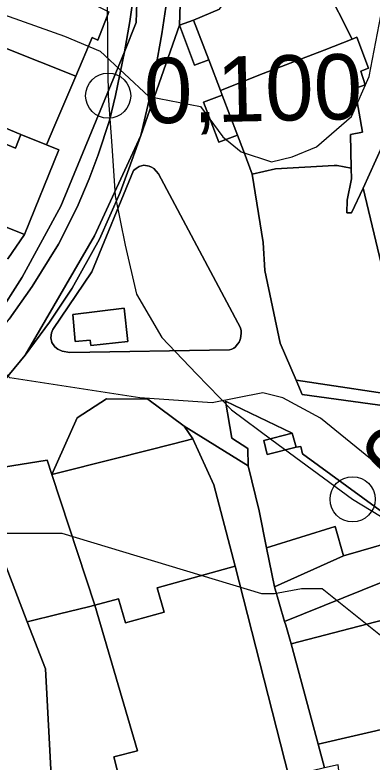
# Model space of a CAD drawing. Extents: x -510989 to -501240, y -1184665 to -1176098.
# Drawn here: x -504684.9 to -504613.7, y -1182308.5 to -1182159.8 of the extents above; entities that cross this region are included whole.
import ezdxf

# ---------------------------------------------------------------- set-up
doc = ezdxf.new("R2010")
doc.units = 0
for name, color, linetype in [('ostatni_plocha_x_ostatni_komunikace', 7, 'Continuous'), ('ostatni_plocha_x_silnice', 7, 'Continuous'), ('ostatni_plocha_x_zelen', 7, 'Continuous'), ('STAV_zaplavove_uzemi', 7, 'Continuous'), ('trasovani_toku', 7, 'Continuous'), ('vrstevnice_01', 7, 'Continuous'), ('vrstevnice_02', 7, 'Continuous'), ('zahrada', 7, 'Continuous'), ('zastavena_plocha_a_nadvori', 7, 'Continuous')]:
    doc.layers.add(name, color=color, linetype=linetype)

msp = doc.modelspace()

# ---------------------------------------------------------------- linework, layer by layer
at = {"layer": 'ostatni_plocha_x_ostatni_komunikace'}
for points in [[(-504644.16, -1182158.62), (-504649.3, -1182160.78), (-504652.14, -1182161.81), (-504650.82, -1182121.52)], [(-504660.37, -1182149.27), (-504662.02, -1182161.09), (-504663.05, -1182167.12), (-504675.77, -1182197.83), (-504683.43, -1182211.95), (-504688.49, -1182219.81)], [(-504611.7, -1182185.91), (-504615.53, -1182194.22), (-504617.83, -1182199.16), (-504618.74, -1182199.13), (-504618.72, -1182196.62), (-504617.81, -1182192.4), (-504617.88, -1182190.27), (-504618.05, -1182183.56), (-504615.66, -1182183.07), (-504617.19, -1182174.42), (-504615.09, -1182173.64), (-504615.99, -1182170.94), (-504614.48, -1182170.36), (-504616.78, -1182164.17), (-504617.71, -1182164.55), (-504623.08, -1182153.88)], [(-504686.3, -1182208.31), (-504682.98, -1182203.49), (-504676.16, -1182186.61), (-504678.6, -1182185.63), (-504676.92, -1182181.68), (-504672.79, -1182171.96), (-504669.53, -1182164.28), (-504668.4, -1182164.75), (-504666.17, -1182159.11)], [(-504697.03, -1182244.56), (-504682.84, -1182227.46), (-504677.99, -1182220.94), (-504673.48, -1182214.15), (-504668.02, -1182204.42), (-504663.93, -1182195.11), (-504662.22, -1182190.36), (-504659.83, -1182183.78), (-504652.14, -1182161.81), (-504649.09, -1182169.74), (-504646.29, -1182168.67), (-504643.94, -1182174.78), (-504643.58, -1182175.72), (-504647.32, -1182177.14), (-504644.29, -1182185.09), (-504640.55, -1182183.66), (-504639.35, -1182186.82), (-504639.21, -1182187.14), (-504637.6, -1182191.44), (-504635.43, -1182205.06), (-504635.12, -1182210.65), (-504632.08, -1182225.08), (-504628.86, -1182232.48), (-504627.64, -1182235.34), (-504603.94, -1182238.59)], [(-504609.96, -1182259.99), (-504627.58, -1182247.12), (-504627.95, -1182245.67), (-504628.83, -1182245.8), (-504629.64, -1182243.02), (-504642.92, -1182236.66), (-504641.7, -1182244.02), (-504638.47, -1182246.06), (-504638.43, -1182249.54), (-504651.18, -1182241.6), (-504658.4, -1182236.23), (-504666.64, -1182236.16), (-504672.47, -1182239.98), (-504677.55, -1182251.26), (-504678.47, -1182248.35), (-504692.63, -1182250.62)]]:
    msp.add_lwpolyline(points, dxfattribs=at)
for points in [[(-504659.22, -1182189.67), (-504660.13, -1182189.92), (-504660.76, -1182190.32), (-504661.28, -1182190.71), (-504669.6, -1182210.92), (-504677.32, -1182222.39), (-504677.62, -1182223.05), (-504677.73, -1182224), (-504677.52, -1182224.94), (-504676.96, -1182225.8), (-504676.36, -1182226.26), (-504675.47, -1182226.7), (-504673.99, -1182226.97), (-504642.15, -1182226.44), (-504641.69, -1182226.31), (-504641.26, -1182226.11), (-504641.02, -1182225.89), (-504640.52, -1182225.31), (-504640.25, -1182224.92), (-504640.09, -1182224.57), (-504639.97, -1182224.15), (-504639.88, -1182223.69), (-504639.82, -1182223.09), (-504639.84, -1182222.64), (-504639.94, -1182222.03), (-504656.29, -1182191.36), (-504657.22, -1182190.32), (-504657.67, -1182190.03), (-504658.16, -1182189.86)], [(-504651.18, -1182241.6), (-504638.43, -1182249.54), (-504636.23, -1182258.44), (-504634.77, -1182265.81), (-504633.21, -1182273.56), (-504631.16, -1182280.51), (-504630.95, -1182281.21), (-504629.89, -1182284.92), (-504629.69, -1182285.64), (-504624.48, -1182304.88), (-504623.21, -1182309.63), (-504630.34, -1182311.33), (-504641.03, -1182269.51), (-504645.27, -1182253.28), (-504649.47, -1182244.16)]]:
    msp.add_lwpolyline(points, close=True, dxfattribs=at)
at = {"layer": 'ostatni_plocha_x_silnice'}
for points in [[(-504650.82, -1182121.52), (-504652.14, -1182161.81), (-504659.83, -1182183.78), (-504658.17, -1182176.68), (-504656.9, -1182170.57), (-504655.64, -1182163.51), (-504654.43, -1182155.52), (-504653.3, -1182146.7), (-504652.48, -1182138.59)], [(-504662.02, -1182161.09), (-504660.37, -1182149.27), (-504660.74, -1182161.27), (-504663.05, -1182167.12)], [(-504659.83, -1182183.78), (-504662.22, -1182190.36), (-504663.93, -1182195.11), (-504668.02, -1182204.42), (-504673.48, -1182214.15), (-504677.99, -1182220.94), (-504682.84, -1182227.46), (-504669.04, -1182203.7)]]:
    msp.add_lwpolyline(points, close=True, dxfattribs=at)
for points in [[(-504766.11, -1182313.77), (-504760.55, -1182307.61), (-504749.86, -1182296.14), (-504746.43, -1182292.4), (-504737.71, -1182282.64), (-504734.35, -1182278.85), (-504728.65, -1182272.06), (-504708.46, -1182247.87), (-504697.85, -1182235.08), (-504692.31, -1182228.28), (-504686.08, -1182220.29), (-504681.44, -1182213.79), (-504676.25, -1182205.38), (-504672.53, -1182198), (-504670.11, -1182192.37), (-504668.31, -1182187.63), (-504666.07, -1182180.74), (-504664.83, -1182175.8), (-504663.05, -1182167.12), (-504660.74, -1182161.27), (-504660.37, -1182149.27)], [(-504654.43, -1182155.52), (-504655.64, -1182163.51), (-504656.9, -1182170.57), (-504658.17, -1182176.68), (-504659.83, -1182183.78), (-504669.04, -1182203.7), (-504682.84, -1182227.46), (-504697.03, -1182244.56), (-504701.01, -1182249.26), (-504722, -1182272.99), (-504747.79, -1182303.57), (-504752.28, -1182308.37), (-504756.37, -1182312.89)], [(-504688.49, -1182219.81), (-504683.43, -1182211.95), (-504675.77, -1182197.83), (-504663.05, -1182167.12), (-504664.83, -1182175.8), (-504666.07, -1182180.74), (-504668.31, -1182187.63), (-504670.11, -1182192.37), (-504672.53, -1182198), (-504676.25, -1182205.38), (-504681.44, -1182213.79), (-504686.08, -1182220.29)]]:
    msp.add_lwpolyline(points, dxfattribs=at)
at = {"layer": 'ostatni_plocha_x_zelen'}
for points in [[(-504649.3, -1182160.78), (-504646.29, -1182168.67), (-504649.09, -1182169.74), (-504652.14, -1182161.81)], [(-504643.58, -1182175.72), (-504640.55, -1182183.66), (-504644.29, -1182185.09), (-504647.32, -1182177.14)], [(-504659.22, -1182189.67), (-504658.16, -1182189.86), (-504657.67, -1182190.03), (-504657.22, -1182190.32), (-504656.29, -1182191.36), (-504639.94, -1182222.03), (-504639.84, -1182222.64), (-504639.82, -1182223.09), (-504639.88, -1182223.69), (-504639.97, -1182224.15), (-504640.09, -1182224.57), (-504640.25, -1182224.92), (-504640.52, -1182225.31), (-504641.02, -1182225.89), (-504641.26, -1182226.11), (-504641.69, -1182226.31), (-504642.15, -1182226.44), (-504673.99, -1182226.97), (-504675.47, -1182226.7), (-504676.36, -1182226.26), (-504676.96, -1182225.8), (-504677.52, -1182224.94), (-504677.73, -1182224), (-504677.62, -1182223.05), (-504677.32, -1182222.39), (-504669.6, -1182210.92), (-504661.28, -1182190.71), (-504660.76, -1182190.32), (-504660.13, -1182189.92)], [(-504673.37, -1182219.36), (-504672.91, -1182224.76), (-504669.9, -1182224.48), (-504669.78, -1182225.58), (-504662.43, -1182224.74), (-504663.12, -1182218.12)]]:
    msp.add_lwpolyline(points, close=True, dxfattribs=at)
at = {"layer": 'STAV_zaplavove_uzemi'}
for points in [[(-502250.32, -1184002.61), (-502355.07, -1183875.41), (-502442.37, -1183790.61), (-502477.29, -1183700.82), (-502532.16, -1183578.61), (-502567.08, -1183448.91), (-502626.05, -1183402.34), (-502705.41, -1183380.59), (-502814.2, -1183349.87), (-502882.03, -1183297.39), (-502931.95, -1183237.24), (-503042.02, -1183107.97), (-503139.64, -1183018.94), (-503222.14, -1182957.59), (-503308.56, -1182839.96), (-503316.24, -1182784.92), (-503330.32, -1182756.77), (-503348.24, -1182719.65), (-503334.16, -1182651.82), (-503323.92, -1182595.5), (-503313.68, -1182526.39), (-503294.1, -1182480.5), (-503251.86, -1182396.03), (-503229.34, -1182314.37), (-503216.1, -1182227.15), (-503242.43, -1182174.5), (-503271.86, -1182129.59), (-503287.34, -1182081.58), (-503343.88, -1182028.1), (-503361.79, -1182008.91), (-503396.35, -1181952.59), (-503442.43, -1181933.39), (-503497.46, -1181888.6), (-503525.62, -1181860.44), (-503528.18, -1181837.4), (-503548.66, -1181767.01), (-503558.9, -1181729.89), (-503576.82, -1181682.53), (-503578.1, -1181621.1), (-503567.86, -1181572.46), (-503552.5, -1181536.63), (-503538.04, -1181458.36), (-503518.33, -1181411.9), (-503509.88, -1181341.51), (-503497.21, -1181207.63), (-503499.77, -1181097.56), (-503498.02, -1181031.35), (-503510.82, -1180970.85), (-503549.22, -1180952.23), (-503571.32, -1180940.6), (-503605.07, -1180937.11), (-503651.61, -1180939.44), (-503671.39, -1180917.33), (-503679.53, -1180892.89), (-503713.27, -1180871.95), (-503727.24, -1180859.15), (-503734.22, -1180833.55), (-503728.4, -1180799.81), (-503741.2, -1180770.72), (-503722.82, -1180725.17), (-503721.54, -1180703.41), (-503731.78, -1180697.01), (-503767.61, -1180699.57), (-503790.65, -1180697.01), (-503817.53, -1180697.01), (-503861.04, -1180686.77), (-503889.2, -1180675.25), (-503900.72, -1180668.85), (-503953.2, -1180679.09), (-503997.99, -1180697.01), (-504063.27, -1180722.61), (-504109.34, -1180749.49), (-504142.62, -1180776.36), (-504177.18, -1180796.84), (-504211.73, -1180817.32), (-504414.98, -1180961.5), (-504472.7, -1180998.11), (-504544.51, -1181068.5), (-504600.82, -1181143.12), (-504621.94, -1181196.62), (-504641.65, -1181267.01), (-504660.25, -1181350.62), (-504634.7, -1181398.32), (-504617.66, -1181447.72), (-504600.62, -1181492.01), (-504587, -1181548.23), (-504592.11, -1181628.29), (-504569.96, -1181682.81), (-504568.26, -1181664.07), (-504554.63, -1181621.48), (-504547.82, -1181597.63)], [(-504826.46, -1182247.73), (-504827.62, -1182204.68), (-504817.15, -1182165.12), (-504791.55, -1182113.93), (-504727.56, -1182034.81), (-504708.94, -1182017.35), (-504669.38, -1181991.76), (-504649.6, -1181961.5), (-504628.66, -1181917.29), (-504601.9, -1181867.26), (-504597.24, -1181809.08), (-504585.16, -1181766.79), (-504596.8, -1181741.4), (-504604.2, -1181726.59), (-504633.82, -1181658.9), (-504646.51, -1181600.72), (-504660.26, -1181556.29), (-504751.04, -1181459.08), (-504798.4, -1181384.84), (-504826.55, -1181347.73), (-504862.39, -1181315.73), (-504866.23, -1181265.81), (-504862.39, -1181205.66), (-504853.43, -1181164.7), (-504793.92, -1181116.47), (-504755.84, -1181064.64), (-504725.17, -1181018.1), (-504649.01, -1180947.23), (-504594, -1180900.69), (-504545.35, -1180879.53), (-504377.38, -1180832.83), (-504317.01, -1180808.36), (-504368.93, -1180802.59), (-504426.63, -1180826.63), (-504542.02, -1180859.32)], [(-504547.82, -1181597.63), (-504529.08, -1181677.7), (-504510.34, -1181762.87), (-504510.34, -1181805.46), (-504503.52, -1181848.05), (-504522.26, -1181902.56), (-504557.31, -1181989.81), (-504582.91, -1182010.28), (-504608.51, -1182029.48), (-504618.75, -1182071.72), (-504632.83, -1182096.04), (-504648.18, -1182115.24), (-504664.82, -1182122.91), (-504685.3, -1182130.59), (-504727.54, -1182144.67), (-504745.46, -1182181.79), (-504758.25, -1182222.75), (-504758.25, -1182257.3), (-504807.19, -1182292.7), (-504828.34, -1182288.47), (-504827.28, -1182244.04)], [(-504574.97, -1181692.93), (-504558.07, -1181754.88), (-504562.29, -1181804.15), (-504563.7, -1181856.24), (-504570.74, -1181913.97), (-504583.41, -1181961.83), (-504617.2, -1182002.66), (-504652.4, -1182051.94), (-504665.07, -1182080.1), (-504696.04, -1182099.81), (-504738.28, -1182108.25), (-504752.36, -1182122.33), (-504767.85, -1182144.86), (-504780.52, -1182142.04), (-504787.55, -1182173.02), (-504781.92, -1182218.07), (-504783.33, -1182247.63), (-504788.96, -1182265.94), (-504808.67, -1182277.2), (-504832.61, -1182281.42)], [(-504824.03, -1182251.79), (-504806.11, -1182251.79), (-504808.67, -1182227.48), (-504803.55, -1182203.16), (-504807.39, -1182181.4), (-504806.11, -1182154.52), (-504795.88, -1182126.36), (-504783.08, -1182119.97), (-504770.28, -1182113.56), (-504754.92, -1182091.81), (-504726.76, -1182079.01), (-504689.64, -1182070.05), (-504667.89, -1182041.89), (-504634.61, -1181997.1), (-504615.41, -1181959.98), (-504602.61, -1181927.98), (-504596.21, -1181880.63), (-504594.68, -1181823.86), (-504583.41, -1181774.59), (-504590.45, -1181740.8), (-504600.31, -1181726.72)]]:
    msp.add_spline(points, degree=3, dxfattribs=at)
at = {"layer": 'trasovani_toku'}
for p, q in [((-504666.52, -1182155.83), (-504666.44, -1182165.83)), ((-504666.44, -1182165.83), (-504666.32, -1182175.83)), ((-504666.32, -1182175.83), (-504665.58, -1182185.81)), ((-504665.58, -1182185.81), (-504664.91, -1182195.78)), ((-504664.91, -1182195.78), (-504662.95, -1182205.59)), ((-504662.95, -1182205.59), (-504660.69, -1182215.33)), ((-504660.69, -1182215.33), (-504655.63, -1182223.96)), ((-504655.63, -1182223.96), (-504648.73, -1182231.19)), ((-504648.73, -1182231.19), (-504641.75, -1182238.36)), ((-504641.75, -1182238.36), (-504633.74, -1182244.34)), ((-504633.74, -1182244.34), (-504625.68, -1182250.25)), ((-504625.68, -1182250.25), (-504617.62, -1182256.17)), ((-504617.62, -1182256.17), (-504609.06, -1182261.35))]:
    msp.add_line(p, q, dxfattribs=at)
for centre in [(-504666.32, -1182175.83), (-504617.62, -1182256.17)]:
    msp.add_circle(centre, 4.5, dxfattribs=at)
at = {"layer": 'vrstevnice_01'}
msp.add_lwpolyline([(-504613, -1182249), (-504624, -1182240), (-504631.5, -1182236), (-504635.5, -1182235), (-504645.59, -1182237), (-504660, -1182236), (-504685.91, -1182232), (-504692.59, -1182225), (-504698.41, -1182222), (-504710.5, -1182217), (-504718.81, -1182216), (-504728.81, -1182218), (-504737, -1182223), (-504749.41, -1182234), (-504775.41, -1182271), (-504783.09, -1182289), (-504788.69, -1182335)], dxfattribs=at)
at = {"layer": 'vrstevnice_02'}
for points in [[(-504689.09, -1182159), (-504675, -1182164), (-504667.91, -1182167), (-504658.19, -1182176), (-504647.91, -1182178), (-504643.5, -1182184), (-504639.81, -1182187), (-504633.81, -1182189), (-504629.69, -1182188), (-504624.81, -1182186), (-504617.81, -1182180), (-504614.31, -1182172), (-504610.69, -1182153)], [(-504602.41, -1182291), (-504623.69, -1182274), (-504627.81, -1182274), (-504633.19, -1182275), (-504635.69, -1182275), (-504675.5, -1182263), (-504691.81, -1182263), (-504700.09, -1182266), (-504704.31, -1182268), (-504708.69, -1182272), (-504713.19, -1182277), (-504723, -1182294), (-504726.81, -1182296), (-504731.59, -1182297), (-504737.09, -1182307), (-504738.5, -1182311), (-504739.41, -1182328)]]:
    msp.add_lwpolyline(points, dxfattribs=at)
at = {"layer": 'zahrada'}
for points in [[(-504628.86, -1182232.48), (-504605, -1182236.03), (-504603.94, -1182238.59), (-504627.64, -1182235.34)], [(-504658.4, -1182236.23), (-504651.18, -1182241.6), (-504649.47, -1182244.16), (-504653.3, -1182245.12), (-504664.58, -1182247.96), (-504677.55, -1182251.26), (-504672.47, -1182239.98), (-504666.64, -1182236.16)], [(-504634.77, -1182265.81), (-504621.06, -1182261.61), (-504619.41, -1182267.4), (-504633.21, -1182273.56)], [(-504615.98, -1182266.42), (-504608.88, -1182264.4), (-504604.03, -1182269.55), (-504631.16, -1182280.51), (-504633.21, -1182273.56), (-504619.41, -1182267.4)], [(-504641.03, -1182269.51), (-504630.34, -1182311.33), (-504641.6, -1182314.32), (-504651.02, -1182316.82), (-504662.04, -1182319.75), (-504665.19, -1182307.45), (-504660.45, -1182306.23), (-504668.96, -1182277.25), (-504664.24, -1182275.96), (-504662.9, -1182280.78), (-504655.19, -1182278.64), (-504656.53, -1182273.82)], [(-504604.03, -1182269.55), (-504600.8, -1182271.69), (-504599.46, -1182277.02), (-504629.89, -1182284.92), (-504630.95, -1182281.21), (-504631.16, -1182280.51)], [(-504668.96, -1182277.25), (-504660.45, -1182306.23), (-504665.19, -1182307.45), (-504662.04, -1182319.75), (-504656.53, -1182341.24), (-504650.6, -1182363.05), (-504641.21, -1182396.51), (-504652.49, -1182400.2), (-504665.38, -1182366.99), (-504669.71, -1182355.06), (-504666.12, -1182354.21), (-504667.75, -1182347.35), (-504670.44, -1182348.03), (-504672.44, -1182341.25), (-504666.74, -1182340.05), (-504671.77, -1182319.92), (-504677.14, -1182321.18), (-504678.79, -1182289.89), (-504682.43, -1182280.53), (-504676.03, -1182278.97), (-504670.23, -1182277.56)], [(-504624.48, -1182304.88), (-504594.03, -1182297.85), (-504589.17, -1182310.48), (-504580.13, -1182308.14), (-504568.81, -1182326.98), (-504579.19, -1182329.55), (-504616.94, -1182338.59), (-504620.51, -1182309), (-504623.21, -1182309.63)]]:
    msp.add_lwpolyline(points, close=True, dxfattribs=at)
at = {"layer": 'zastavena_plocha_a_nadvori'}
for points in [[(-504711.71, -1182141.93), (-504701.67, -1182146.31), (-504695.74, -1182148.63), (-504695.54, -1182148.01), (-504687.85, -1182150.74), (-504687.76, -1182150.51), (-504687.55, -1182149.95), (-504668.12, -1182157.54), (-504668.31, -1182158.11), (-504666.96, -1182158.74), (-504666.17, -1182159.11), (-504668.4, -1182164.75), (-504669.53, -1182164.28), (-504672.79, -1182171.96), (-504694, -1182163.49), (-504705.94, -1182158.72), (-504715.12, -1182155.48), (-504715.65, -1182155.38)], [(-504648.89, -1182150.8), (-504644.34, -1182145.17), (-504633.92, -1182153.64), (-504633.22, -1182152.88), (-504627.69, -1182153.39), (-504623.08, -1182153.88), (-504617.71, -1182164.55), (-504623.29, -1182166.79), (-504635.41, -1182171.42), (-504643.94, -1182174.78), (-504646.29, -1182168.67), (-504649.3, -1182160.78), (-504644.16, -1182158.62), (-504642.51, -1182156.21)], [(-504726, -1182152.98), (-504715.65, -1182155.38), (-504715.12, -1182155.48), (-504705.94, -1182158.72), (-504694, -1182163.49), (-504672.79, -1182171.96), (-504676.92, -1182181.68), (-504678.6, -1182185.63), (-504683.69, -1182183.57), (-504716.35, -1182169.88), (-504731.55, -1182165.9), (-504731.77, -1182165.83)], [(-504617.71, -1182164.55), (-504616.78, -1182164.17), (-504614.48, -1182170.36), (-504615.99, -1182170.94), (-504615.09, -1182173.64), (-504617.19, -1182174.42), (-504615.66, -1182183.07), (-504618.05, -1182183.56), (-504617.88, -1182190.27), (-504620.68, -1182189.73), (-504621.26, -1182189.75), (-504632.97, -1182190.37), (-504637.6, -1182191.44), (-504639.21, -1182187.14), (-504639.35, -1182186.82), (-504640.55, -1182183.66), (-504643.58, -1182175.72), (-504643.94, -1182174.78), (-504635.41, -1182171.42), (-504623.29, -1182166.79)], [(-504721.13, -1182181.96), (-504716.35, -1182169.88), (-504683.69, -1182183.57), (-504684.8, -1182186.31), (-504689.28, -1182184.41), (-504694.94, -1182198.66), (-504682.98, -1182203.49), (-504686.3, -1182208.31), (-504723.8, -1182196.37)], [(-504597.73, -1182176.87), (-504597.21, -1182182.31), (-504596.03, -1182181.82), (-504593.9, -1182191.1), (-504591.54, -1182190.6), (-504587.72, -1182208.5), (-504610.49, -1182215.33), (-504615.53, -1182194.22), (-504611.7, -1182185.91), (-504611.49, -1182183.57), (-504612.01, -1182178.25)], [(-504683.69, -1182183.57), (-504678.6, -1182185.63), (-504676.16, -1182186.61), (-504682.98, -1182203.49), (-504694.94, -1182198.66), (-504689.28, -1182184.41), (-504684.8, -1182186.31)], [(-504621.26, -1182189.75), (-504620.68, -1182189.73), (-504617.88, -1182190.27), (-504617.81, -1182192.4), (-504618.72, -1182196.62), (-504618.74, -1182199.13), (-504617.83, -1182199.16), (-504615.53, -1182194.22), (-504610.49, -1182215.33), (-504608.19, -1182222.37), (-504609.46, -1182225.23), (-504605, -1182236.03), (-504628.86, -1182232.48), (-504632.08, -1182225.08), (-504635.12, -1182210.65), (-504635.43, -1182205.06), (-504637.6, -1182191.44), (-504632.97, -1182190.37)], [(-504673.37, -1182219.36), (-504663.12, -1182218.12), (-504662.43, -1182224.74), (-504669.78, -1182225.58), (-504669.9, -1182224.48), (-504672.91, -1182224.76)], [(-504642.92, -1182236.66), (-504629.64, -1182243.02), (-504635.32, -1182244.49), (-504634.61, -1182247.28), (-504628.83, -1182245.8), (-504627.95, -1182245.67), (-504627.58, -1182247.12), (-504609.96, -1182259.99), (-504608.88, -1182264.4), (-504615.98, -1182266.42), (-504619.41, -1182267.4), (-504621.06, -1182261.61), (-504634.77, -1182265.81), (-504636.23, -1182258.44), (-504638.43, -1182249.54), (-504638.47, -1182246.06), (-504641.7, -1182244.02)], [(-504653.3, -1182245.12), (-504649.47, -1182244.16), (-504645.27, -1182253.28), (-504641.03, -1182269.51), (-504656.53, -1182273.82), (-504655.19, -1182278.64), (-504662.9, -1182280.78), (-504664.24, -1182275.96), (-504668.96, -1182277.25), (-504677.55, -1182251.26), (-504664.58, -1182247.96)], [(-504635.32, -1182244.49), (-504629.64, -1182243.02), (-504628.83, -1182245.8), (-504634.61, -1182247.28)], [(-504678.47, -1182248.35), (-504677.55, -1182251.26), (-504668.96, -1182277.25), (-504670.23, -1182277.56), (-504676.03, -1182278.97), (-504682.43, -1182280.53), (-504688.84, -1182264.02), (-504689.35, -1182262.23), (-504691.95, -1182253.01), (-504692.63, -1182250.62)], [(-504697.4, -1182267.48), (-504688.84, -1182264.02), (-504682.43, -1182280.53), (-504678.79, -1182289.89), (-504677.14, -1182321.18), (-504672.44, -1182341.25), (-504670.44, -1182348.03), (-504672.29, -1182348.47), (-504682.24, -1182350.8), (-504686.8, -1182326.98), (-504690.01, -1182304.64), (-504692.64, -1182294.12), (-504694.34, -1182287.92), (-504696.41, -1182285.71), (-504699.87, -1182282.02), (-504696.65, -1182278.27), (-504700.94, -1182269.81), (-504701.61, -1182268.61), (-504697.8, -1182267.64)], [(-504629.89, -1182284.92), (-504599.46, -1182277.02), (-504596.96, -1182284.92), (-504594.03, -1182297.85), (-504624.48, -1182304.88), (-504629.69, -1182285.64)]]:
    msp.add_lwpolyline(points, close=True, dxfattribs=at)

# ---------------------------------------------------------------- texts
at = {"layer": 'trasovani_toku'}
for s, rotation, p in [('0,100', 1.2325, (-504659.08, -1182181.39)), ('0,200', 56.8325, (-504605.81, -1182255.17))]:
    msp.add_text(s, height=13, rotation=rotation, dxfattribs=at).set_placement(p)

doc.saveas('drawing.dxf')
